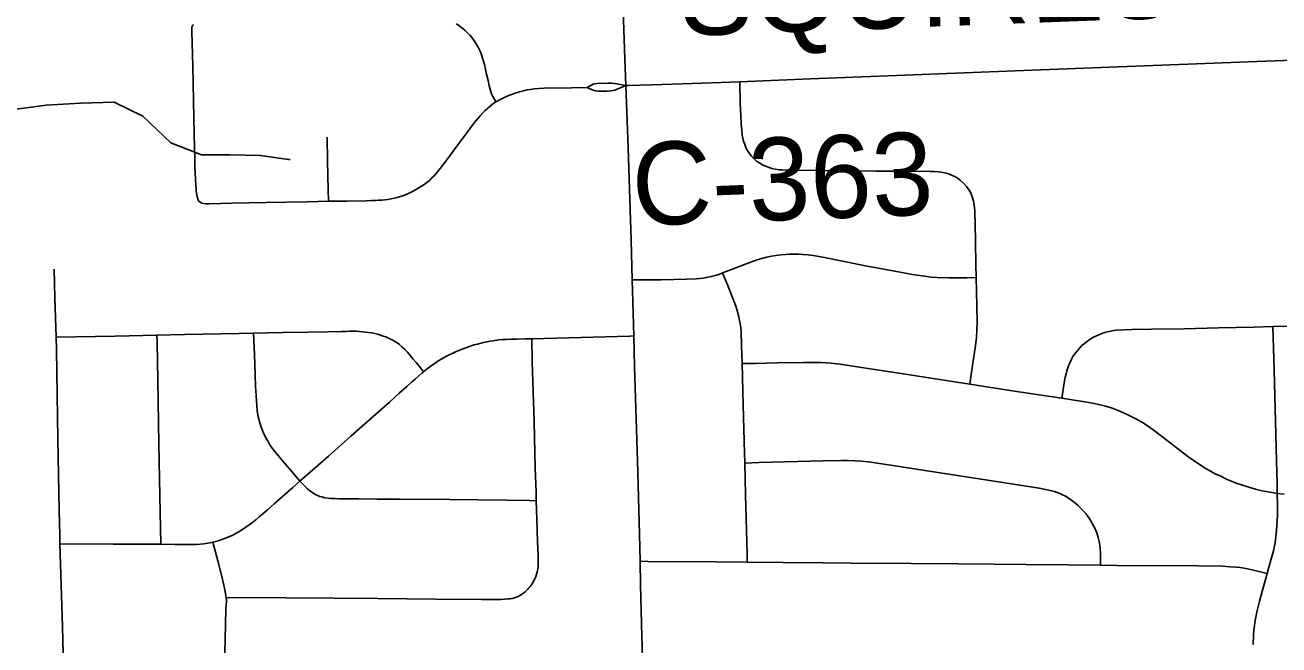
# Model space of a CAD drawing. Extents: x -6.4 to 34, y -4.2 to 22.
# Drawn here: x 5.066 to 5.927, y 18.659 to 19.085 of the extents above; entities that cross this region are included whole.
import ezdxf

# ---------------------------------------------------------------- set-up
doc = ezdxf.new("R2010")
doc.units = 0
for name, color, linetype in [('GM_X_County_Road', 7, 'Continuous'), ('GM_X_County_Road_Text', 7, 'Continuous'), ('GM_X_Minor_River', 7, 'Continuous'), ('GM_X_State_Route', 7, 'Continuous'), ('GM_X_Township_Road', 7, 'Continuous')]:
    doc.layers.add(name, color=color, linetype=linetype)

msp = doc.modelspace()

# ---------------------------------------------------------------- linework, layer by layer
at = {"layer": 'GM_X_County_Road'}
msp.add_lwpolyline([(5.47867, 19.04325), (5.48027, 19.0433), (5.49663, 19.04381), (5.53098, 19.04482), (5.55676, 19.0458), (5.60504, 19.04782), (5.66432, 19.05028), (5.71076, 19.05199), (5.75747, 19.05381), (5.91163, 19.05971), (5.97992, 19.06244), (5.98704, 19.06272)], dxfattribs=at)
at = {"layer": 'GM_X_Minor_River'}
msp.add_lwpolyline([(4.99291, 19.01437), (5.0198, 19.01947), (5.04006, 19.02262), (5.05843, 19.0268), (5.08079, 19.02973), (5.10427, 19.03114), (5.12737, 19.03179), (5.147, 19.0222), (5.16619, 19.00388), (5.18734, 18.9958), (5.20665, 18.99571), (5.22785, 18.99523), (5.24714, 18.99248), (5.24828, 18.99248)], dxfattribs=at)
at = {"layer": 'GM_X_State_Route'}
for points in [[(5.48836, 18.71663), (5.48791, 18.73529), (5.48659, 18.7857), (5.48463, 18.85017), (5.48401, 18.87134), (5.48354, 18.88706), (5.48292, 18.9098), (5.48217, 18.93716), (5.48113, 18.9723), (5.4803, 19.00052), (5.47867, 19.04325), (5.47797, 19.0616), (5.47672, 19.09493)], [(5.49974, 18.28524), (5.49947, 18.29424), (5.49898, 18.31187), (5.49805, 18.34585), (5.49729, 18.3757), (5.49706, 18.38339), (5.49645, 18.40383), (5.4956, 18.43406), (5.49476, 18.46872), (5.49392, 18.49915), (5.4933, 18.52152), (5.49236, 18.56048), (5.49147, 18.5949), (5.49055, 18.6298), (5.48979, 18.65889), (5.48963, 18.66496), (5.48876, 18.70053), (5.48836, 18.71663)]]:
    msp.add_lwpolyline(points, dxfattribs=at)
at = {"layer": 'GM_X_Township_Road'}
for points in [[(5.18504, 18.96453), (5.18471, 18.96527), (5.18446, 18.96609), (5.1843, 18.96691), (5.18405, 18.96815), (5.18389, 18.9693), (5.18373, 18.97087), (5.18356, 18.97267), (5.1834, 18.97464), (5.18315, 18.97868), (5.18294, 18.98354), (5.18282, 18.98757), (5.18267, 18.99332), (5.18235, 19.00943), (5.1821, 19.02153), (5.18187, 19.0328), (5.18135, 19.05657), (5.18075, 19.08033), (5.18075, 19.08181), (5.18076, 19.08305), (5.18092, 19.08404), (5.18133, 19.08478)], [(5.18133, 19.08478), (5.18183, 19.08527)], [(5.36223, 19.08567), (5.36379, 19.08468), (5.36519, 19.08369), (5.36667, 19.08254), (5.36832, 19.08114), (5.36996, 19.07957), (5.37147, 19.07794), (5.37284, 19.07629), (5.37424, 19.07447), (5.37496, 19.0734), (5.37588, 19.07193), (5.37664, 19.07073), (5.37752, 19.06912), (5.37841, 19.06734), (5.37908, 19.06584), (5.3798, 19.06377), (5.38031, 19.06221), (5.38085, 19.06013), (5.38148, 19.05771), (5.3822, 19.05456), (5.38299, 19.05112), (5.384, 19.04667), (5.38482, 19.04313), (5.3854, 19.04083), (5.38589, 19.0391), (5.38638, 19.0377), (5.38681, 19.03672), (5.38729, 19.03573), (5.38794, 19.03458), (5.3894, 19.03202)], [(5.18504, 18.96453), (5.18545, 18.96396), (5.18643, 18.96313), (5.1876, 18.96251), (5.18875, 18.96227), (5.19032, 18.96218), (5.19246, 18.96218), (5.20824, 18.96258), (5.23177, 18.96306), (5.25982, 18.96356), (5.27445, 18.96388), (5.2873, 18.96401), (5.30046, 18.96425), (5.30398, 18.96432), (5.30669, 18.9644), (5.30859, 18.96448), (5.31114, 18.96465), (5.31327, 18.96489), (5.31516, 18.96514), (5.31739, 18.96547), (5.31961, 18.96588), (5.32166, 18.96637), (5.3238, 18.96703), (5.32586, 18.96777), (5.32791, 18.96859), (5.3303, 18.96965), (5.3322, 18.97056), (5.33417, 18.97162), (5.33615, 18.97277), (5.33828, 18.97417), (5.34012, 18.9754), (5.3419, 18.97672), (5.34372, 18.9782), (5.34519, 18.9796), (5.34692, 18.98132), (5.34915, 18.98387), (5.3512, 18.98641), (5.3557, 18.99236), (5.36265, 19.0017), (5.36678, 19.00726), (5.37145, 19.01354), (5.3731, 19.01576), (5.37475, 19.01792), (5.37607, 19.01954), (5.37722, 19.02094), (5.37854, 19.0225), (5.38033, 19.0245), (5.38199, 19.02612), (5.38357, 19.0276), (5.38547, 19.02925), (5.38709, 19.03047), (5.38874, 19.03162), (5.3894, 19.03202), (5.39063, 19.03277), (5.39228, 19.03368), (5.39409, 19.03458), (5.39623, 19.03557), (5.39869, 19.03663), (5.40083, 19.03746), (5.40306, 19.03819), (5.4056, 19.03902), (5.40824, 19.03975), (5.41054, 19.04025), (5.41313, 19.04069), (5.41589, 19.04098), (5.41893, 19.04122), (5.42247, 19.04139), (5.44122, 19.04162), (5.45213, 19.04193), (5.45394, 19.0411), (5.45567, 19.04028), (5.4569, 19.03987), (5.45813, 19.03962), (5.45953, 19.0395), (5.4611, 19.03947), (5.46554, 19.03953), (5.46834, 19.03969), (5.46981, 19.03984), (5.47114, 19.0401), (5.47867, 19.04325)], [(5.45213, 19.04193), (5.45403, 19.04308), (5.45502, 19.04365), (5.45608, 19.04414), (5.45748, 19.04455), (5.45896, 19.04472), (5.46628, 19.04504), (5.46867, 19.04495), (5.47089, 19.0447), (5.47867, 19.04325)], [(5.71476, 18.83821), (5.71595, 18.84644), (5.71867, 18.86469), (5.71925, 18.87012), (5.71958, 18.87563), (5.71975, 18.88065), (5.71959, 18.89232), (5.7191, 18.91152), (5.71895, 18.92021), (5.71856, 18.93591), (5.7184, 18.9485), (5.71821, 18.95514), (5.71809, 18.95743), (5.71792, 18.95928), (5.71772, 18.96082), (5.71748, 18.96242), (5.71723, 18.9639), (5.71685, 18.96528), (5.71643, 18.9668), (5.71586, 18.96818), (5.71508, 18.96982), (5.71421, 18.9714), (5.71254, 18.97387), (5.71058, 18.97614), (5.70838, 18.97815), (5.70596, 18.97988), (5.70376, 18.98112), (5.7017, 18.98205), (5.70002, 18.98268), (5.69843, 18.98316), (5.69652, 18.98359), (5.69473, 18.9839), (5.69294, 18.98411), (5.69041, 18.98428), (5.68744, 18.98438), (5.66514, 18.98454), (5.65025, 18.98461), (5.61215, 18.98488), (5.59183, 18.98515), (5.58903, 18.98519), (5.58595, 18.98531), (5.58376, 18.9855), (5.5812, 18.98587), (5.57877, 18.98643), (5.57689, 18.98697), (5.57454, 18.98791), (5.57232, 18.98896), (5.57053, 18.98995), (5.56838, 18.9914), (5.56708, 18.99248), (5.56597, 18.99355), (5.56486, 18.99476), (5.56386, 18.99599), (5.56295, 18.9973), (5.5621, 18.99868), (5.56129, 19.00013), (5.56068, 19.00154), (5.55996, 19.00341), (5.5594, 19.00514), (5.55891, 19.00717), (5.55854, 19.00919), (5.55813, 19.01255), (5.5578, 19.01684), (5.55754, 19.02271), (5.55717, 19.03067), (5.55676, 19.0458)], [(5.27445, 18.96388), (5.2743, 18.97166), (5.27391, 18.99133), (5.27351, 19.00786)], [(5.48292, 18.9098), (5.48867, 18.90983), (5.50275, 18.90989), (5.52013, 18.91033), (5.52691, 18.91059), (5.52946, 18.91079), (5.53193, 18.91112), (5.53464, 18.91161), (5.53719, 18.91212), (5.53983, 18.91276), (5.54247, 18.91365), (5.54488, 18.91459), (5.55225, 18.91745), (5.56368, 18.92178), (5.56874, 18.92362), (5.57205, 18.92457), (5.57528, 18.92536), (5.57851, 18.92603), (5.58162, 18.92654), (5.58499, 18.92695), (5.5882, 18.92728), (5.591, 18.92744), (5.59396, 18.92749), (5.59717, 18.92744), (5.60024, 18.92729), (5.60366, 18.92702), (5.6071, 18.92657), (5.61386, 18.92536), (5.64434, 18.91937), (5.66328, 18.91588), (5.67528, 18.91365), (5.68351, 18.91233), (5.68812, 18.91183), (5.69231, 18.9115), (5.70021, 18.91125), (5.71273, 18.91135), (5.7191, 18.91152)], [(5.10012, 18.30734), (5.10004, 18.31168), (5.09937, 18.35251), (5.09804, 18.40451), (5.09727, 18.44534), (5.0964, 18.48629), (5.09503, 18.53169), (5.09383, 18.58729), (5.09279, 18.63458), (5.09184, 18.67184), (5.09016, 18.72851), (5.09007, 18.73468), (5.08967, 18.75153), (5.0888, 18.80039), (5.08769, 18.86191), (5.08746, 18.87048), (5.08673, 18.89735), (5.08616, 18.91718)], [(5.56197, 18.71609), (5.56186, 18.7216), (5.56077, 18.76228), (5.56018, 18.78406), (5.56, 18.79102), (5.55911, 18.82384), (5.55838, 18.85242), (5.55807, 18.8648), (5.55766, 18.8741), (5.55742, 18.87706), (5.55709, 18.87961), (5.55668, 18.88208), (5.55619, 18.88455), (5.55504, 18.88874), (5.55381, 18.89252), (5.55233, 18.89664), (5.54784, 18.90769), (5.54488, 18.91459)], [(5.77792, 18.82853), (5.77978, 18.84058), (5.78027, 18.84312), (5.78075, 18.8453), (5.78138, 18.84744), (5.78199, 18.84943), (5.78274, 18.85157), (5.78355, 18.85344), (5.78453, 18.85545), (5.78553, 18.85714), (5.78663, 18.85878), (5.78791, 18.86043), (5.79022, 18.86322), (5.79169, 18.86476), (5.7931, 18.86602), (5.79458, 18.86719), (5.79631, 18.8684), (5.79786, 18.86938), (5.79971, 18.87043), (5.80323, 18.87216), (5.80539, 18.87296), (5.80742, 18.87365), (5.80934, 18.87419), (5.8115, 18.87468), (5.81353, 18.87505), (5.81573, 18.87529), (5.82029, 18.87558), (5.82584, 18.87578), (5.83949, 18.87596), (5.86178, 18.87627), (5.88551, 18.87685), (5.90961, 18.87749), (5.92273, 18.87781), (5.94572, 18.87837)], [(5.90933, 18.65951), (5.90947, 18.66577), (5.90972, 18.6693), (5.91004, 18.6726), (5.91054, 18.67596), (5.9112, 18.67934), (5.91195, 18.68279), (5.91359, 18.68929), (5.91541, 18.69587), (5.91878, 18.70828), (5.91994, 18.71256), (5.92307, 18.72391), (5.92423, 18.72958), (5.92506, 18.73542), (5.92547, 18.74069), (5.92581, 18.74825), (5.9259, 18.75533), (5.92574, 18.76328), (5.92559, 18.76991), (5.92527, 18.7857), (5.92452, 18.81278), (5.92356, 18.84777), (5.92273, 18.87781)], [(5.08746, 18.87048), (5.12803, 18.87128), (5.15669, 18.87184), (5.17557, 18.87232), (5.21324, 18.87311), (5.22308, 18.87329), (5.2431, 18.87367), (5.26061, 18.87398), (5.27385, 18.87422), (5.28331, 18.87438), (5.28619, 18.87449), (5.28899, 18.87454), (5.29146, 18.87454), (5.2936, 18.87454), (5.29576, 18.87445), (5.29788, 18.87425), (5.30001, 18.87404), (5.30198, 18.87379), (5.3042, 18.87346), (5.30618, 18.87305), (5.30807, 18.87255), (5.3102, 18.87198), (5.3121, 18.87132), (5.31374, 18.87066), (5.31522, 18.87), (5.31703, 18.86917), (5.31859, 18.86835), (5.31991, 18.86761), (5.32163, 18.86654), (5.32312, 18.86539), (5.32484, 18.8639), (5.32657, 18.86234), (5.32862, 18.8602), (5.33076, 18.85773), (5.33265, 18.85543), (5.33456, 18.85314), (5.33684, 18.85041), (5.33978, 18.84678)], [(5.09016, 18.72851), (5.12668, 18.72848), (5.15941, 18.72846), (5.16896, 18.72823), (5.17471, 18.72815), (5.17751, 18.72812), (5.18088, 18.72812), (5.18392, 18.7282), (5.18639, 18.72835), (5.18894, 18.72868), (5.19165, 18.72909), (5.19329, 18.72941), (5.19519, 18.7298), (5.19684, 18.73024), (5.19864, 18.73073), (5.20053, 18.73131), (5.20268, 18.73205), (5.20539, 18.73311), (5.20712, 18.73385), (5.20885, 18.73468), (5.21049, 18.7355), (5.21255, 18.73665), (5.21551, 18.73846), (5.21781, 18.74001), (5.22078, 18.74215), (5.22259, 18.74355), (5.22456, 18.74511), (5.22687, 18.74708), (5.22941, 18.7493), (5.23255, 18.75201), (5.23712, 18.756), (5.24269, 18.76085), (5.24991, 18.76738), (5.25492, 18.77176), (5.27451, 18.78891), (5.2899, 18.80247), (5.30521, 18.81603), (5.31632, 18.82598), (5.32307, 18.83206), (5.32817, 18.83666), (5.33154, 18.83961), (5.33402, 18.84175), (5.33673, 18.84414), (5.33887, 18.84603), (5.33978, 18.84678), (5.34125, 18.848), (5.34315, 18.84948), (5.34521, 18.85096), (5.34693, 18.85219), (5.34858, 18.85334), (5.35022, 18.85441), (5.35236, 18.85572), (5.35508, 18.85729), (5.3573, 18.85844), (5.35927, 18.85942), (5.36166, 18.86049), (5.36397, 18.86147), (5.36618, 18.86237), (5.36799, 18.86303), (5.36989, 18.86369), (5.37244, 18.86451), (5.37458, 18.86516), (5.37688, 18.86582), (5.38, 18.86664), (5.38181, 18.86706), (5.38338, 18.86738), (5.38543, 18.86779), (5.38757, 18.86812), (5.39119, 18.86861), (5.39399, 18.86886), (5.3967, 18.86902), (5.39999, 18.86913), (5.40403, 18.86926), (5.40954, 18.86935), (5.41395, 18.86942), (5.43133, 18.86981), (5.45617, 18.87054), (5.48134, 18.87126), (5.48401, 18.87134)], [(5.15941, 18.72846), (5.15878, 18.76128), (5.15807, 18.79739), (5.15736, 18.84073), (5.1568, 18.86664), (5.15669, 18.87184)], [(5.22308, 18.87329), (5.22374, 18.85894), (5.22413, 18.84472), (5.22446, 18.83699), (5.22478, 18.83049), (5.225, 18.8267), (5.22527, 18.82341), (5.2256, 18.8202), (5.22609, 18.817), (5.22658, 18.81453), (5.22707, 18.81247), (5.22756, 18.81091), (5.2283, 18.80877), (5.22912, 18.80655), (5.22995, 18.80458), (5.23101, 18.80244), (5.232, 18.80054), (5.23274, 18.79923), (5.23348, 18.79799), (5.2343, 18.79668), (5.23521, 18.79528), (5.2361, 18.79404), (5.23742, 18.79232), (5.23906, 18.79033), (5.24107, 18.78792), (5.24317, 18.7854), (5.2461, 18.782), (5.24921, 18.77839), (5.25492, 18.77176), (5.25772, 18.76878), (5.2588, 18.76773), (5.26018, 18.76639), (5.26175, 18.76507), (5.26339, 18.76384), (5.26512, 18.76277), (5.26652, 18.76203), (5.26849, 18.7612), (5.26988, 18.76079), (5.27186, 18.7603), (5.27417, 18.75997), (5.27605, 18.7598), (5.27899, 18.75967), (5.28148, 18.75956), (5.28469, 18.75946), (5.28946, 18.75946), (5.29522, 18.75946), (5.30797, 18.75937), (5.32318, 18.75928), (5.35772, 18.759), (5.39712, 18.75855), (5.41249, 18.75831), (5.4171, 18.75823)], [(5.41798, 18.71018), (5.41814, 18.71141), (5.4183, 18.71297), (5.41839, 18.71453), (5.41839, 18.71667), (5.41832, 18.72062), (5.41791, 18.72983), (5.41742, 18.74581), (5.4171, 18.75823), (5.41694, 18.76423), (5.41646, 18.78025), (5.41566, 18.81273), (5.41429, 18.85361), (5.41395, 18.86942)], [(5.55838, 18.85242), (5.56768, 18.85254), (5.58266, 18.85292), (5.60034, 18.85323), (5.60659, 18.85323), (5.61284, 18.85306), (5.61926, 18.85264), (5.62575, 18.85198), (5.64335, 18.84925), (5.6677, 18.84549), (5.69391, 18.84143), (5.71476, 18.83821), (5.7249, 18.83664), (5.74538, 18.83348), (5.7607, 18.83113), (5.77792, 18.82853), (5.79208, 18.82645), (5.79775, 18.82546), (5.80317, 18.82439), (5.80803, 18.82315), (5.81312, 18.8215), (5.81765, 18.81977), (5.82233, 18.81771), (5.82816, 18.81475), (5.8336, 18.81163), (5.84059, 18.80692), (5.8473, 18.80181), (5.86447, 18.78854), (5.87103, 18.78392), (5.87622, 18.78063), (5.87955, 18.77869), (5.88324, 18.77678), (5.88695, 18.77499), (5.89102, 18.77306), (5.89747, 18.77037), (5.90183, 18.7688), (5.90619, 18.76749), (5.91088, 18.76617), (5.91548, 18.76509), (5.92083, 18.76402), (5.92574, 18.76328), (5.93045, 18.76278)], [(5.56018, 18.78406), (5.57004, 18.78436), (5.6138, 18.78567), (5.62608, 18.78587), (5.63118, 18.78587), (5.63578, 18.7857), (5.64031, 18.78536), (5.64507, 18.78488), (5.66357, 18.78211), (5.68981, 18.77806), (5.7181, 18.77369), (5.76223, 18.76686), (5.76675, 18.76603), (5.77086, 18.76512), (5.77281, 18.76458), (5.77472, 18.76389), (5.77651, 18.76317), (5.77834, 18.76232), (5.78029, 18.76137), (5.78212, 18.76027), (5.78541, 18.75788), (5.78886, 18.75508), (5.79166, 18.75228), (5.79429, 18.7494), (5.79599, 18.74712), (5.79771, 18.74441), (5.79902, 18.74219), (5.80053, 18.73944), (5.80193, 18.73616), (5.80291, 18.73294), (5.80373, 18.72941), (5.80423, 18.72554), (5.80447, 18.72209), (5.80453, 18.7183), (5.80452, 18.71396)], [(5.20352, 18.6621), (5.20355, 18.66312), (5.20412, 18.68368), (5.20429, 18.68689), (5.20437, 18.68878), (5.20437, 18.69026), (5.20425, 18.69185), (5.2041, 18.69282), (5.20388, 18.69438), (5.20331, 18.69717), (5.20265, 18.70022), (5.20093, 18.70721), (5.19847, 18.71683), (5.19519, 18.7298)], [(5.48836, 18.71663), (5.49363, 18.71659), (5.54039, 18.71622), (5.56197, 18.71609), (5.58665, 18.71586), (5.61372, 18.71561), (5.63297, 18.7154), (5.67447, 18.71513), (5.70682, 18.71492), (5.73088, 18.71466), (5.7531, 18.71454), (5.7822, 18.71418), (5.80452, 18.71396), (5.8156, 18.71385), (5.87163, 18.71349), (5.88836, 18.71317), (5.89325, 18.71292), (5.8976, 18.7126), (5.90033, 18.71226), (5.90308, 18.71185), (5.90847, 18.71078), (5.91878, 18.70828)], [(5.20425, 18.69185), (5.24522, 18.69156), (5.27845, 18.69137), (5.3083, 18.69103), (5.34811, 18.69058), (5.37985, 18.6904), (5.38973, 18.69039), (5.39285, 18.69048), (5.3954, 18.69055), (5.39754, 18.69075), (5.39902, 18.69088), (5.4005, 18.69113), (5.40206, 18.69154), (5.40322, 18.69195), (5.4047, 18.69252), (5.40593, 18.69318), (5.40708, 18.69383), (5.40831, 18.69474), (5.40939, 18.69564), (5.41029, 18.69646), (5.4113, 18.69743), (5.4121, 18.69836), (5.41284, 18.69926), (5.41375, 18.7005), (5.41465, 18.70181), (5.41531, 18.70296), (5.41581, 18.70411), (5.41647, 18.70559), (5.41699, 18.70698), (5.41745, 18.70847), (5.41798, 18.71018)], [(5.19067, 18.30463), (5.19087, 18.30832), (5.19229, 18.33423), (5.19331, 18.35362), (5.19403, 18.36729), (5.19537, 18.39492), (5.1968, 18.44106), (5.19857, 18.49929), (5.19975, 18.54313), (5.20118, 18.59215), (5.20286, 18.64067), (5.20352, 18.6621)]]:
    msp.add_lwpolyline(points, dxfattribs=at)

# ---------------------------------------------------------------- texts
at = {"layer": 'GM_X_County_Road_Text'}
for s, rotation, p in [('SQUIRES', 2.14444, (5.51596, 19.07728)), ('C-363', 2.20232, (5.48371, 18.94695))]:
    msp.add_text(s, height=0.056818, rotation=rotation, dxfattribs=at).set_placement(p)

doc.saveas('drawing.dxf')
